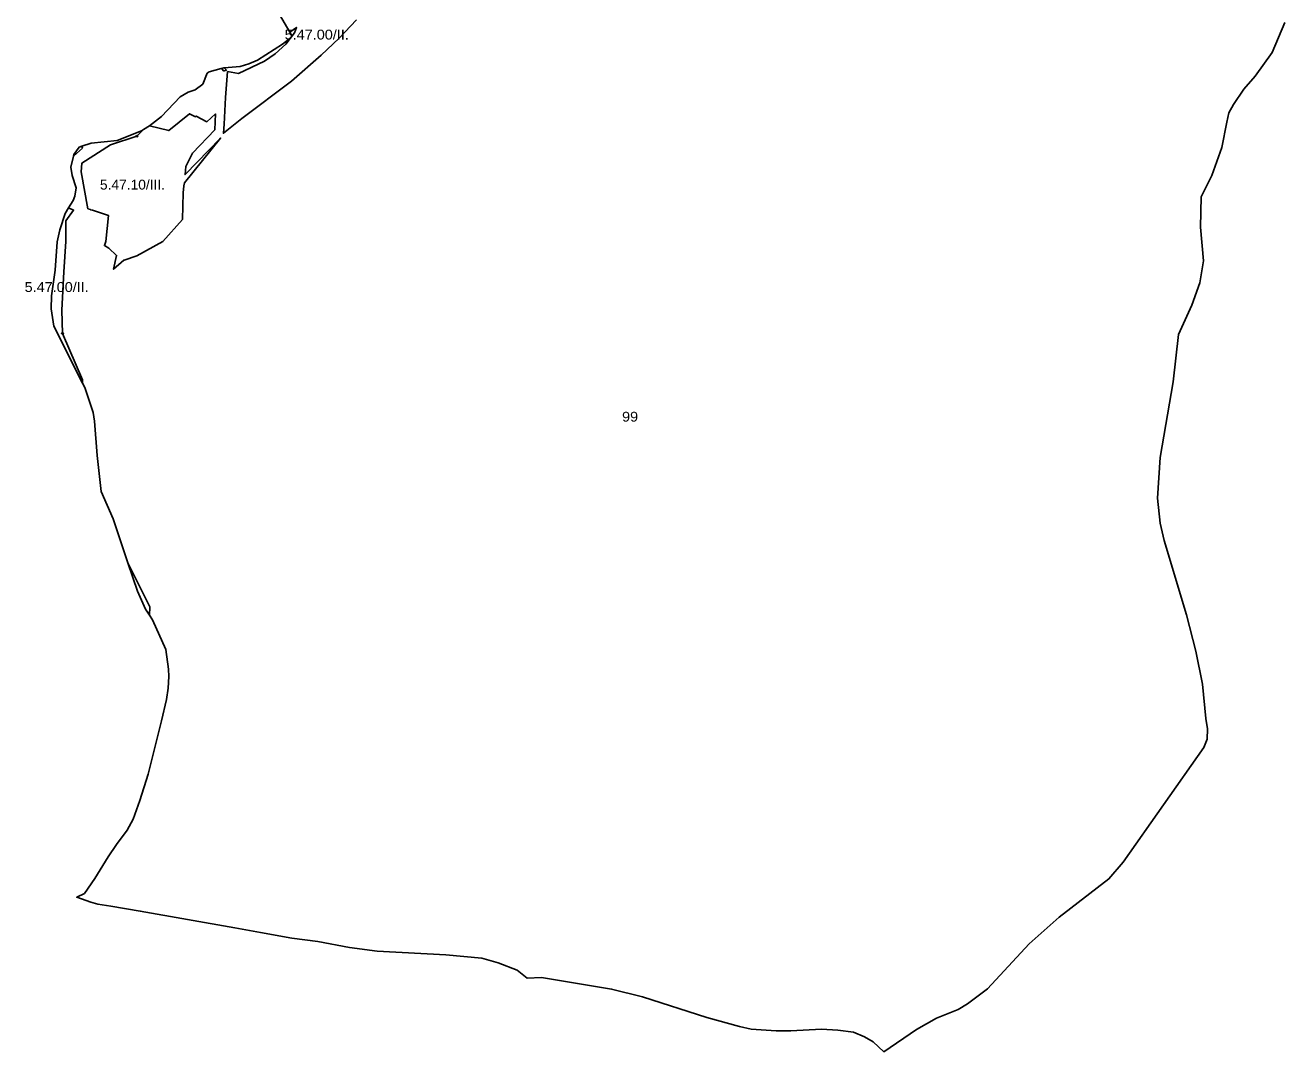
# Model space of a CAD drawing. Extents: x -650455 to -642254, y -1075222 to -1066610.
# Drawn here: x -649050 to -647766, y -1075222 to -1074176 of the extents above; entities that cross this region are included whole.
import ezdxf
from ezdxf.enums import TextEntityAlignment as Align

# ---------------------------------------------------------------- set-up
doc = ezdxf.new("R2010")
doc.units = 0
doc.header["$LTSCALE"] = 4
doc.header["$PDMODE"] = 32
doc.header["$PDSIZE"] = 2
for name, color, linetype, lineweight in [('1', 7, 'Continuous', 25), ('12', 7, 'Continuous', 13), ('13', 7, 'Continuous', 13)]:
    doc.layers.add(name, color=color, linetype=linetype, lineweight=lineweight)
doc.layers.add('2', color=7, linetype='Continuous')

msp = doc.modelspace()

# ---------------------------------------------------------------- linework, layer by layer
at = {"layer": '1'}
for points in [[(-648904, -1074283.5), (-648923.613, -1074278.483), (-648911.565, -1074269.193), (-648892.342, -1074248.943), (-648884.125, -1074244.247), (-648877.081, -1074241.752), (-648869.304, -1074236.03), (-648864.902, -1074225.026), (-648862.962, -1074223.588), (-648850.49, -1074220.137), (-648849.67, -1074221.011), (-648848.28, -1074222.49), (-648847.65, -1074222.603), (-648845.34, -1074221.77), (-648847.426, -1074219.41), (-648831.299, -1074217.982), (-648822.495, -1074215.34), (-648813.69, -1074211.526), (-648788.011, -1074195.237), (-648780.234, -1074189.367), (-648778.426, -1074187.092), (-648780.692, -1074183.167), (-648773.97, -1074178.261), (-648775.93, -1074183.911), (-648784.8, -1074195.26), (-648795.65, -1074205.351), (-648806.55, -1074212.621), (-648833.11, -1074225.201), (-648844.05, -1074223.243), (-648844.4, -1074227.801), (-648846.06, -1074249.88), (-648847.75, -1074276.773), (-648848.34, -1074286.15), (-648829.66, -1074270.99), (-648778.97, -1074232.99), (-648748.74, -1074206.61), (-648730.34, -1074189.22), (-648712.77, -1074170.511)], [(-648712.77, -1074170.511), (-648730.34, -1074189.22), (-648748.74, -1074206.61), (-648778.97, -1074232.99), (-648829.66, -1074270.99), (-648848.34, -1074286.15), (-648847.75, -1074276.773), (-648846.06, -1074249.88), (-648844.4, -1074227.801), (-648844.05, -1074223.243), (-648833.11, -1074225.201), (-648806.55, -1074212.621), (-648795.65, -1074205.351), (-648784.8, -1074195.26), (-648775.93, -1074183.911), (-648773.97, -1074178.261), (-648780.692, -1074183.167), (-648793.41, -1074161.141)], [(-647766.475, -1074173.244), (-647779.502, -1074203.89), (-647796.756, -1074227.844), (-647808.375, -1074241.23), (-647818.938, -1074256.729), (-647823.515, -1074265.183), (-647825.694, -1074274.886), (-647830.623, -1074300.601), (-647840.834, -1074329.133), (-647851.749, -1074350.972), (-647852.453, -1074381.971), (-647849.284, -1074416.141), (-647853.157, -1074438.684), (-647861.255, -1074461.228), (-647874.987, -1074491.17), (-647880.268, -1074539.428), (-647893.647, -1074616.572), (-647896.111, -1074657.786), (-647893.647, -1074683.5), (-647889.421, -1074701.114), (-647866.534, -1074776.849), (-647857.027, -1074813.835), (-647850.337, -1074847.3), (-647846.815, -1074882.524), (-647845.221, -1074892.842), (-647845.769, -1074903.457), (-647849.163, -1074912.038), (-647931.068, -1075028.922)], [(-648992, -1074301.501), (-648992.574, -1074299.204), (-648983.32, -1074296.194), (-648956.614, -1074293.698), (-648931.962, -1074283.573), (-648929.699, -1074282.2), (-648936.5, -1074289.001), (-648963.5, -1074298.001), (-648992.5, -1074316.5), (-648993.5, -1074325.501), (-648986.5, -1074363.001), (-648983.669, -1074363.943), (-648983.61, -1074364.28), (-648981.95, -1074364.52), (-648981.933, -1074364.523), (-648965.5, -1074370.001), (-648968.141, -1074396.414), (-648969.59, -1074400.58), (-648965.1, -1074403.2), (-648957.239, -1074410.6), (-648960.37, -1074424.701), (-648949.75, -1074415.441), (-648949.67, -1074415.391), (-648936.5, -1074411.001), (-648910, -1074396.5), (-648890, -1074374.001), (-648889.5, -1074347.001), (-648888.69, -1074339.711), (-648888.06, -1074336.58), (-648851.16, -1074291.13), (-648887.42, -1074328.31), (-648886.5, -1074320), (-648880, -1074306.501), (-648857, -1074282.501), (-648856.5, -1074266.5), (-648865.35, -1074274.371), (-648876.21, -1074268.73), (-648876.892, -1074269.292), (-648883, -1074266.5), (-648904, -1074283.5)], [(-648989.955, -1075060.702), (-648979.565, -1075045.589), (-648965.931, -1075023.453), (-648957.308, -1075010.734), (-648946.461, -1074996.229), (-648940.313, -1074984.954), (-648933.709, -1074966.044), (-648925.17, -1074939.163), (-648911.393, -1074884.942), (-648906.383, -1074863.072), (-648904.675, -1074851.568), (-648903.878, -1074839.721), (-648904.22, -1074832.09), (-648907.066, -1074812.269), (-648920.534, -1074781.84), (-648923.788, -1074777), (-648923.5, -1074768.5), (-648945.63, -1074723.877), (-648960.635, -1074678.95), (-648972.901, -1074651.007), (-648977.157, -1074614.616), (-648979.652, -1074579.398), (-648981.119, -1074570.595), (-648989.776, -1074545.061), (-648991.916, -1074540.822), (-648992, -1074537.501), (-649012.5, -1074490), (-649013, -1074466.5), (-649011, -1074427.501), (-649009, -1074396.5), (-649009, -1074375.501), (-649001, -1074364.5), (-649006.103, -1074362.204), (-649001.369, -1074354.595), (-648999.754, -1074350.193), (-648998.581, -1074341.683), (-649002.396, -1074329.357), (-649003.716, -1074320.845), (-649001.227, -1074309.642), (-648992, -1074301.501)], [(-647931.068, -1075028.922), (-647945.678, -1075045.792), (-647996.448, -1075084.953), (-648027.007, -1075112.056), (-648069.62, -1075157.855), (-648089.831, -1075173.202), (-648099.449, -1075178.988), (-648121.364, -1075187.881), (-648141.818, -1075199.391), (-648175.178, -1075221.987), (-648186.014, -1075211.998), (-648195.024, -1075206.699), (-648206.103, -1075201.949), (-648222.174, -1075199.878), (-648238.61, -1075198.965), (-648270.144, -1075200.731), (-648284.998, -1075200.731), (-648310.566, -1075198.843), (-648322.375, -1075196.285), (-648355.735, -1075186.967), (-648421.237, -1075165.894), (-648452.77, -1075158.16), (-648524.116, -1075146.406), (-648538.604, -1075147.014), (-648548.953, -1075138.853), (-648568.311, -1075131.241), (-648585.113, -1075126.733), (-648621.691, -1075123.255), (-648691.575, -1075119.357), (-648719.699, -1075115.764), (-648751.963, -1075109.736), (-648778.505, -1075106.143), (-648810.561, -1075100.367), (-648836.816, -1075095.565), (-648933.142, -1075078.591), (-648963.202, -1075073.729), (-648976.238, -1075071.7), (-648983.525, -1075069.593), (-648997.809, -1075064.448), (-648989.955, -1075060.702)]]:
    msp.add_lwpolyline(points, dxfattribs=at)
for points in [[(-648845.34, -1074221.77), (-648847.65, -1074222.603), (-648848.28, -1074222.49), (-648849.67, -1074221.011), (-648850.49, -1074220.137), (-648848.07, -1074219.467), (-648847.426, -1074219.41)], [(-648929.699, -1074282.2), (-648923.744, -1074278.584), (-648923.613, -1074278.483), (-648904, -1074283.5), (-648883, -1074266.5), (-648876.892, -1074269.292), (-648876.21, -1074268.73), (-648865.35, -1074274.371), (-648856.5, -1074266.5), (-648857, -1074282.501), (-648880, -1074306.501), (-648886.5, -1074320), (-648887.42, -1074328.31), (-648851.16, -1074291.13), (-648888.06, -1074336.58), (-648888.69, -1074339.711), (-648889.5, -1074347.001), (-648890, -1074374.001), (-648910, -1074396.5), (-648936.5, -1074411.001), (-648949.67, -1074415.391), (-648949.75, -1074415.441), (-648960.37, -1074424.701), (-648957.239, -1074410.6), (-648965.1, -1074403.2), (-648969.59, -1074400.58), (-648968.141, -1074396.414), (-648965.5, -1074370.001), (-648981.933, -1074364.523), (-648981.95, -1074364.52), (-648983.61, -1074364.28), (-648983.669, -1074363.943), (-648986.5, -1074363.001), (-648993.5, -1074325.501), (-648992.5, -1074316.5), (-648963.5, -1074298.001), (-648936.5, -1074289.001)], [(-648992, -1074301.501), (-649001.227, -1074309.642), (-649000.782, -1074307.639), (-648995.499, -1074300.156), (-648992.574, -1074299.204)], [(-648992, -1074537.501), (-648991.916, -1074540.822), (-649021.325, -1074482.551), (-649023.82, -1074464.943), (-649023.673, -1074451.736), (-649019.711, -1074425.617), (-649017.657, -1074396.855), (-649015.016, -1074384.529), (-649009.586, -1074367.802), (-649006.103, -1074362.204), (-649001, -1074364.5), (-649009, -1074375.501), (-649009, -1074396.5), (-649011, -1074427.501), (-649013, -1074466.5), (-649012.5, -1074490)], [(-648923.5, -1074768.5), (-648923.788, -1074777), (-648927.751, -1074771.104), (-648935.982, -1074752.766), (-648945.63, -1074723.877)]]:
    msp.add_lwpolyline(points, close=True, dxfattribs=at)
at = {"layer": '12'}
for points in [[(-648793.41, -1074161.141), (-648780.692, -1074183.167), (-648773.97, -1074178.261), (-648775.93, -1074183.911), (-648784.8, -1074195.26), (-648795.65, -1074205.351), (-648806.55, -1074212.621), (-648833.11, -1074225.201), (-648844.05, -1074223.243), (-648844.4, -1074227.801), (-648846.06, -1074249.88), (-648847.75, -1074276.773), (-648848.34, -1074286.15), (-648829.66, -1074270.99), (-648778.97, -1074232.99), (-648748.74, -1074206.61), (-648730.34, -1074189.22), (-648712.77, -1074170.511)], [(-649012.5, -1074490), (-649013, -1074466.5), (-649011, -1074427.501), (-649009, -1074396.5), (-649009, -1074375.501), (-649001, -1074364.5), (-649006.103, -1074362.204), (-649009.586, -1074367.802), (-649015.016, -1074384.529), (-649017.657, -1074396.855), (-649019.711, -1074425.617), (-649023.673, -1074451.736), (-649023.82, -1074464.943), (-649021.325, -1074482.551), (-648991.916, -1074540.822)], [(-648991.916, -1074540.822), (-648992, -1074537.501), (-649012.5, -1074490)]]:
    msp.add_lwpolyline(points, dxfattribs=at)
msp.add_point((-649012.5, -1074490), dxfattribs=at)
at = {"layer": '13'}
for points in [[(-648910, -1074396.5), (-648890, -1074374.001), (-648889.5, -1074347.001), (-648888.69, -1074339.711), (-648888.06, -1074336.58), (-648851.16, -1074291.13), (-648887.42, -1074328.31), (-648886.5, -1074320), (-648880, -1074306.501), (-648857, -1074282.501), (-648856.5, -1074266.5), (-648865.35, -1074274.371), (-648876.21, -1074268.73), (-648876.892, -1074269.292), (-648883, -1074266.5), (-648904, -1074283.5), (-648923.613, -1074278.483), (-648923.744, -1074278.584), (-648929.699, -1074282.2), (-648936.5, -1074289.001)], [(-648936.5, -1074289.001), (-648963.5, -1074298.001), (-648992.5, -1074316.5), (-648993.5, -1074325.501), (-648986.5, -1074363.001), (-648983.669, -1074363.943), (-648983.61, -1074364.28), (-648981.95, -1074364.52), (-648981.933, -1074364.523), (-648965.5, -1074370.001), (-648968.141, -1074396.414), (-648969.59, -1074400.58), (-648965.1, -1074403.2), (-648957.239, -1074410.6), (-648960.37, -1074424.701), (-648949.75, -1074415.441), (-648949.67, -1074415.391), (-648936.5, -1074411.001), (-648910, -1074396.5)]]:
    msp.add_lwpolyline(points, dxfattribs=at)
msp.add_point((-648936.5, -1074289.001), dxfattribs=at)

# ---------------------------------------------------------------- texts
at = {"layer": '2'}
for s, width, p in [('5.47.00/II.', 1.1, (-648753.213, -1074190.644)), ('5.47.10/III.', 1.05, (-648941.034, -1074343.51)), ('5.47.00/II.', 1.1, (-649018.278, -1074447.826)), ('99', 1.1, (-648433.836, -1074579.942))]:
    msp.add_text(s, height=10, dxfattribs=dict(at, width=width)).set_placement(p, align=Align.CENTER)

doc.saveas('drawing.dxf')
